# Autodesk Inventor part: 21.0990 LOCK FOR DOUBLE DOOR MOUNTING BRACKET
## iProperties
Created: 2007-03
Part Number: 21.0990 LOCK FOR DOUBLE DOOR MOUNTING BRACKET
Document SubType Name: Modeling
Designer: Andy Moles
Material: Aluminum-6061
Density: 2.71 g/cm^3
Author: Andy Moles
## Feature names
1. Base1
2. Hole1
3. Hole2
4. Hole3
5. Hole4
